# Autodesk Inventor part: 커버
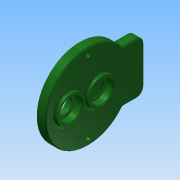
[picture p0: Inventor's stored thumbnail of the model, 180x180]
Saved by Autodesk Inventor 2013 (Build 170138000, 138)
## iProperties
Created: 2016-02
Part Number: 커버
Material: 알루미늄 6061
Document SubType Name: Modeling
Designer: mduedu
Density: 1 g/cm^3
Author: mduedu
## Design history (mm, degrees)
sketch "스케치1"
  geometry: C1 r 43 at (0, 0); 1 further point
  constraints: 1 centre point, 1 coincident
  dimensions: "d0" = 86 diameter of C1
extrude "돌출1" new body sketch "스케치1" distance "d1" = 9; taper "d2" = 0 deg
sketch "스케치2"
  geometry: C1 r 14 at (0, 11); 1 further point
  constraints: 1 centre point, 1 vertical alignment
  dimensions: "d3" = 28 diameter of C1; "d6" = 11 distance of C1.centre point (0, 0)
extrude "돌출2" join sketch "스케치2" distance "d7" = 3; taper "d8" = 0 deg
sketch "스케치3"
  geometry: C1 r 14 at (0, -20); 1 further point
  constraints: 1 centre point, 1 vertical alignment
  dimensions: "d9" = 28 diameter of C1; "d10" = 20 distance of C1.centre point (0, 0)
extrude "돌출3" join sketch "스케치3" distance "d11" = 3; taper "d12" = 0 deg
hole "구멍1" diameter "d15" = 22; stored, may be unused: countersink angle "d19" = 90 deg, drill point angle "d21" = 0 deg; dims "d13" = 10, "d14" = 10, "d16" = 6, "d17" = 4, "d18" = 2, "d20" = 7
hole "구멍2" diameter "d24" = 18; stored, may be unused: countersink angle "d28" = 90 deg, drill point angle "d30" = 0 deg; dims "d22" = 10, "d23" = 10, "d25" = 6, "d26" = 4, "d27" = 2, "d29" = 1
hole "구멍3" diameter "d33" = 22; stored, may be unused: countersink angle "d37" = 90 deg, drill point angle "d39" = 0 deg; dims "d34" = 6, "d35" = 4, "d36" = 2, "d38" = 7, "d73" = 10, "d74" = 10
sketch "스케치7"
  geometry: L1 (-26, 34.249)-(26, 34.249); L2 (26, 34.249)-(26, 56); L3 (26, 56)-(-26, 56); L4 (-26, 56)-(-26, 34.249); A1 r 43 centre (0, 0) between (-26, 34.249) and (26, 34.249) reference; 1 further point
  constraints: 8 end point, 2 parallel, 2 point on circle, 1 horizontal, 1 perpendicular
  dimensions: "d95" = 52 distance of L2.end L3.end; "d97" = 56 distance from line of L3 point (0, 0)
extrude "돌출5" join sketch "스케치7" stored distance "d98" = 10; taper "d99" = 0 deg
sketch "스케치4"
  geometry: C1 r 14 at (0, -20) reference; C2 r 18 at (0, -20); 1 further point
  constraints: 1 centre point, 1 coincident
  dimensions: "d40" = 36 diameter of C2
extrude "돌출4" join sketch "스케치4" distance "d41" = 4; taper "d42" = 0 deg
hole "구멍4" diameter "d45" = 22; stored, may be unused: countersink angle "d49" = 90 deg, drill point angle "d51" = 0 deg; dims "d43" = 10, "d44" = 10, "d46" = 6, "d47" = 4, "d48" = 2, "d50" = 7
hole "구멍5" diameter "d54" = 15; stored, may be unused: countersink angle "d58" = 90 deg, drill point angle "d60" = 0 deg; dims "d52" = 10, "d53" = 10, "d55" = 6, "d56" = 4, "d57" = 2, "d59" = 7
fillet "모깎기1" dims "d61" = 0.3
fillet "모깎기2" dims "d62" = 2
chamfer "모따기1" distance "d63" = 1; stored, may be unused: second distance "d64" = 2, angle "d65" = 45 deg
fillet "모깎기6" dims "d88" = 2
sketch "스케치5" dims "d67" = 72
  geometry: 4 further points
  constraints: 2 horizontal alignment, 1 coincident, 5 other
  dimensions: "d71" = 360 deg dimension on point (0, 0) point (-36, 0) (derived)
fillet "모깎기4" dims "d75" = 2
sketch "스케치6"
  geometry: 2 further points
hole "구멍6" sketch "스케치6" at (36, 0), (-36, 0) diameter "d76" = 4.5; stored, may be unused: countersink angle "d80" = 90 deg, drill point angle "d82" = 0 deg; dims "d77" = 6, "d78" = 8, "d79" = 4.6, "d81" = 8
fillet "모깎기7" dims "d100" = 8, "d101" = 2
chamfer "모따기2" distance "d90" = 1; stored, may be unused: second distance "d91" = 2, angle "d92" = 45 deg
node "솔리드1"
node "절단 모서리 투영1"
